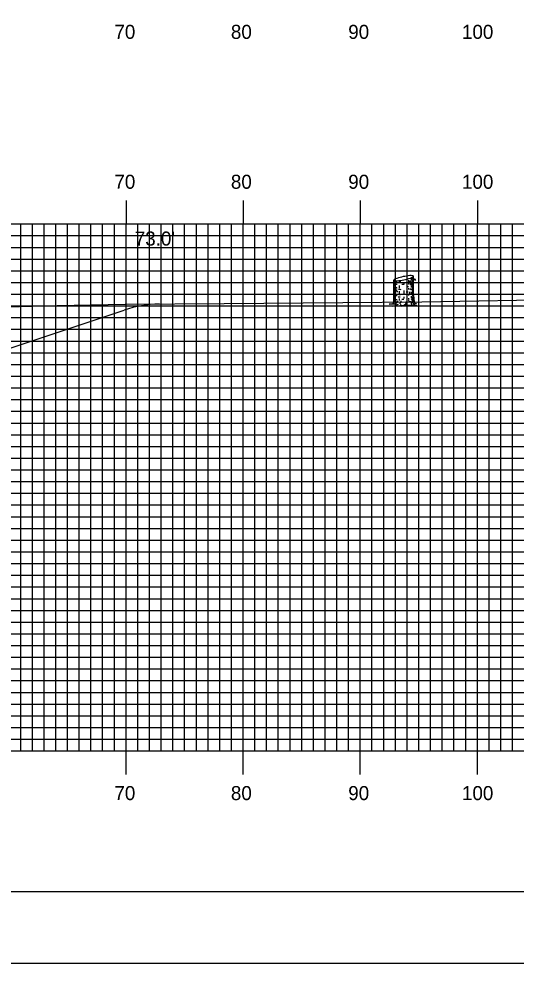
# Model space of a CAD drawing. Extents: x 1795633 to 1795976, y 442591 to 442811.
# Drawn here: x 1795859.7 to 1795902.2, y 442590.5 to 442671.2 of the extents above; entities that cross this region are included whole.
import ezdxf

# ---------------------------------------------------------------- set-up
doc = ezdxf.new("R2010")
doc.units = 0
for name, color, linetype in [('BORDER', 7, 'Continuous'), ('D_Roadway_SlopeLines', 7, 'Continuous'), ('D_Text_Standard', 7, 'Continuous'), ('H_V ANNOTATION', 7, 'Continuous'), ('M_Trees_Conifer_Pay', 7, 'Continuous'), ('MAJOR', 7, 'Continuous'), ('MINOR', 7, 'Continuous'), ('PLOT BOUNDARY', 7, 'Continuous'), ('S_Roadway_Centerline', 7, 'Continuous')]:
    doc.layers.add(name, color=color, linetype=linetype)

msp = doc.modelspace()

# ---------------------------------------------------------------- linework, layer by layer
at = {"layer": 'BORDER'}
msp.add_lwpolyline([(1795649.279, 442596.665), (1795969.279, 442596.665), (1795969.279, 442806.665), (1795649.279, 442806.665)], close=True, dxfattribs=at)
at = {"layer": 'D_Roadway_SlopeLines'}
msp.add_lwpolyline([(1795838.888, 442638.365), (1795844.888, 442638.365), (1795868.728, 442646.312)], dxfattribs=at)
msp.add_arc((1795871.949, 442636.647), 10.187, 91.37379, 108.43495, dxfattribs=at)
at = {"layer": 'M_Trees_Conifer_Pay'}
for p, q in [((1795891.746, 442647.137), (1795891.746, 442648.858)), ((1795891.793, 442648.821), (1795891.793, 442648.35)), ((1795891.852, 442648.81), (1795891.852, 442648.712)), ((1795891.852, 442648.638), (1795891.852, 442648.434)), ((1795891.977, 442648.802), (1795891.977, 442648.57)), ((1795892.197, 442648.822), (1795892.197, 442648.654)), ((1795892.993, 442648.864), (1795892.993, 442648.665)), ((1795893.221, 442649.061), (1795893.221, 442648.837)), ((1795893.221, 442648.749), (1795893.221, 442648.702)), ((1795893.339, 442649.122), (1795893.339, 442648.959)), ((1795893.339, 442648.891), (1795893.339, 442648.763)), ((1795893.41, 442647.547), (1795893.41, 442649.194)), ((1795891.793, 442648.286), (1795891.793, 442647.977)), ((1795891.793, 442647.93), (1795891.793, 442647.438)), ((1795891.852, 442648.376), (1795891.852, 442648.177)), ((1795891.852, 442648.129), (1795891.852, 442647.794)), ((1795891.977, 442648.529), (1795891.977, 442648.455)), ((1795891.977, 442648.051), (1795891.977, 442647.913)), ((1795892.197, 442648.418), (1795892.197, 442648.181)), ((1795892.197, 442647.936), (1795892.197, 442647.784)), ((1795892.603, 442648.591), (1795892.603, 442648.496)), ((1795892.603, 442647.977), (1795892.603, 442647.903)), ((1795892.603, 442647.878), (1795892.603, 442647.73)), ((1795892.993, 442648.607), (1795892.993, 442648.519)), ((1795892.993, 442648.171), (1795892.993, 442648.066)), ((1795893.221, 442648.366), (1795893.221, 442648.234)), ((1795893.221, 442648.124), (1795893.221, 442648.014)), ((1795893.221, 442647.878), (1795893.221, 442647.736)), ((1795893.278, 442648.566), (1795893.227, 442648.506)), ((1795893.339, 442648.576), (1795893.339, 442648.24)), ((1795893.339, 442648.204), (1795893.339, 442648.041)), ((1795893.339, 442647.994), (1795893.339, 442647.777)), ((1795891.793, 442647.384), (1795891.793, 442647.137)), ((1795891.852, 442647.74), (1795891.852, 442647.605)), ((1795891.852, 442647.505), (1795891.852, 442647.127)), ((1795891.977, 442647.641), (1795891.977, 442647.5)), ((1795891.977, 442647.238), (1795891.977, 442647.143)), ((1795892.197, 442647.74), (1795892.197, 442647.567)), ((1795892.197, 442647.29), (1795892.197, 442647.137)), ((1795892.603, 442647.438), (1795892.603, 442647.285)), ((1795892.993, 442647.699), (1795892.993, 442647.553)), ((1795892.993, 442647.32), (1795892.993, 442647.232)), ((1795893.221, 442647.509), (1795893.221, 442647.337)), ((1795893.339, 442647.746), (1795893.339, 442647.672)), ((1795893.339, 442647.631), (1795893.339, 442647.458)), ((1795891.977, 442646.744), (1795892.14, 442646.807)), ((1795892.414, 442646.679), (1795892.288, 442646.744))]:
    msp.add_line(p, q, dxfattribs=at)
for points in [[(1795893.194, 442648.654), (1795893.163, 442648.57), (1795893.159, 442648.502), (1795893.19, 442648.439)], [(1795893.227, 442648.692), (1795893.264, 442648.618), (1795893.311, 442648.675), (1795893.369, 442648.743), (1795893.461, 442648.937), (1795893.526, 442648.984), (1795893.557, 442648.99)], [(1795893.242, 442648.439), (1795893.278, 442648.566), (1795893.342, 442648.681), (1795893.373, 442648.749), (1795893.442, 442648.895)], [(1795893.456, 442648.925), (1795893.532, 442648.933), (1795893.604, 442648.834)], [(1795891.925, 442648.164), (1795891.919, 442648.259), (1795891.963, 442648.236), (1795891.963, 442648.142)], [(1795893.064, 442647.765), (1795893.077, 442647.689), (1795893.124, 442647.699), (1795893.112, 442647.866)], [(1795893.41, 442647.547), (1795893.461, 442647.285), (1795893.478, 442647.011), (1795893.536, 442646.886), (1795893.671, 442646.855), (1795893.441, 442646.818), (1795893.441, 442646.818), (1795893.447, 442646.771), (1795893.694, 442646.676), (1795893.42, 442646.692), (1795893.064, 442646.713), (1795892.743, 442646.702), (1795892.749, 442646.785), (1795892.601, 442646.702), (1795892.414, 442646.679), (1795892.438, 442646.612), (1795892.171, 442646.655), (1795891.95, 442646.628), (1795891.658, 442646.645), (1795891.946, 442646.702), (1795891.977, 442646.744), (1795891.814, 442646.801), (1795891.578, 442646.812), (1795891.337, 442646.812), (1795891.679, 442646.87), (1795891.72, 442646.95), (1795891.746, 442647.137)], [(1795891.794, 442647.089), (1795891.773, 442647.011), (1795891.753, 442646.917)], [(1795891.872, 442647.069), (1795891.878, 442646.954), (1795891.825, 442646.865), (1795891.814, 442646.801)], [(1795892.035, 442647.096), (1795892.035, 442646.964), (1795891.946, 442646.865)], [(1795892.261, 442646.855), (1795892.329, 442646.95), (1795892.356, 442647.089)], [(1795892.749, 442646.785), (1795892.824, 442646.927), (1795892.833, 442647.028)], [(1795893, 442647.154), (1795893.011, 442647.028), (1795893.085, 442646.984)], [(1795893.278, 442646.765), (1795893.264, 442646.902), (1795893.19, 442647.032)], [(1795893.237, 442647.259), (1795893.311, 442647.154), (1795893.316, 442646.981), (1795893.441, 442646.818)], [(1795893.336, 442647.404), (1795893.342, 442647.259), (1795893.389, 442647.19), (1795893.4, 442646.991)]]:
    msp.add_lwpolyline(points, dxfattribs=at)
for centre, radius, start, end in [((1795891.778, 442648.68), 0.0334, 163.94846, 180), ((1795891.778, 442648.68), 0.0334, 180, 196.05154), ((1795891.773, 442648.858), 0.0264, 169.2194, 180.03145), ((1795891.769, 442648.858), 0.0226, 180.03145, 191.7194), ((1795891.789, 442648.683), 0.0441, 196.05154, 210), ((1795891.778, 442648.857), 0.0314, 156.51582, 169.2194), ((1795891.769, 442648.858), 0.0226, 191.7194, 203.40735), ((1795891.772, 442648.86), 0.0264, 203.40735, 214.2194), ((1795891.797, 442648.849), 0.0527, 146.7194, 156.51582), ((1795891.777, 442648.862), 0.0314, 214.2194, 226.92298), ((1795891.805, 442648.692), 0.0624, 210, 228.74941), ((1795891.821, 442648.833), 0.0817, 132.38868, 146.7194), ((1795891.791, 442648.878), 0.0527, 226.92298, 236.7194), ((1795891.807, 442648.902), 0.0817, 236.7194, 251.05013), ((1795891.877, 442648.775), 0.172, 228.74941, 240), ((1795891.935, 442648.708), 0.251, 124.2194, 132.38868), ((1795891.862, 442649.062), 0.251, 251.05013, 259.2194), ((1795892.245, 442648.252), 0.802, 108.05939, 124.2194), ((1795891.965, 442649.603), 0.802, 259.2194, 275.37941), ((1795893.602, 442644.091), 5.179, 101.7194, 108.05939), ((1795891.555, 442653.961), 5.179, 275.37941, 281.7194), ((1795892.578, 442652.87), 4.124, 264.6955, 266.73309), ((1795893.602, 442644.091), 5.179, 95.37941, 101.7194), ((1795891.555, 442653.961), 5.179, 281.7194, 288.05939), ((1795892.578, 442652.87), 4.124, 276.23804, 278.1032), ((1795893.192, 442648.449), 0.802, 79.2194, 95.37941), ((1795892.912, 442649.8), 0.802, 288.05939, 304.2194), ((1795893.079, 442649.353), 0.571, 278.1032, 284.36665), ((1795893.079, 442649.507), 0.571, 284.43166, 292.41325), ((1795893.079, 442649.353), 0.571, 297.0237, 300), ((1795893.295, 442648.99), 0.251, 71.05013, 79.2194), ((1795893.221, 442649.344), 0.251, 304.2194, 312.38868), ((1795893.279, 442649.162), 0.172, 300, 311.25059), ((1795893.279, 442649.008), 0.172, 300, 311.25059), ((1795893.35, 442649.15), 0.0817, 56.7194, 71.05013), ((1795893.335, 442649.219), 0.0817, 312.38868, 326.7194), ((1795893.351, 442649.08), 0.0624, 311.25059, 330), ((1795893.351, 442648.925), 0.0624, 311.25059, 330), ((1795893.366, 442649.174), 0.0527, 46.92298, 56.7194), ((1795893.38, 442649.19), 0.0314, 34.2194, 46.92298), ((1795893.359, 442649.203), 0.0527, 326.7194, 336.51582), ((1795893.367, 442649.07), 0.0441, 330, 343.94846), ((1795893.367, 442648.916), 0.0441, 330, 343.94846), ((1795893.384, 442649.192), 0.0264, 23.40735, 34.2194), ((1795893.388, 442649.194), 0.0226, 11.7194, 23.40735), ((1795893.379, 442649.195), 0.0314, 336.51582, 349.2194), ((1795893.377, 442649.068), 0.0334, 343.94846, 354.21506), ((1795893.377, 442648.913), 0.0334, 343.94846, 354.21506), ((1795893.388, 442649.194), 0.0226, 0.03145, 11.7194), ((1795893.384, 442649.194), 0.0264, 349.2194, 0.03145), ((1795891.778, 442648.233), 0.0334, 163.94846, 180), ((1795891.778, 442648.233), 0.0334, 180, 196.05154), ((1795891.778, 442648.023), 0.0334, 163.94846, 180), ((1795891.778, 442648.023), 0.0334, 180, 196.05154), ((1795891.789, 442648.236), 0.0441, 196.05154, 210), ((1795891.789, 442648.026), 0.0441, 196.05154, 210), ((1795891.805, 442648.246), 0.0624, 210, 228.74941), ((1795891.805, 442648.035), 0.0624, 210, 228.74941), ((1795891.877, 442648.328), 0.172, 228.74941, 240), ((1795891.877, 442648.118), 0.172, 228.74941, 240), ((1795892.076, 442649.12), 0.571, 240, 240.33672), ((1795892.076, 442648.673), 0.571, 240, 240.33672), ((1795892.076, 442648.463), 0.571, 240, 246.85973), ((1795892.078, 442648.909), 0.571, 240, 247.05866), ((1795892.076, 442649.12), 0.571, 246.85973, 257.98457), ((1795892.076, 442648.463), 0.571, 259.27072, 261.8968), ((1795892.577, 442651.981), 4.124, 261.8968, 263.14738), ((1795892.577, 442652.191), 4.124, 264.08098, 266.66759), ((1795892.577, 442652.638), 4.124, 268.07512, 270), ((1795892.577, 442652.638), 4.124, 270, 270.35814), ((1795892.577, 442651.981), 4.124, 270, 270.35814), ((1795892.577, 442651.981), 4.124, 273.14934, 275.45691), ((1795892.578, 442652.426), 4.124, 273.70524, 275.95043), ((1795892.577, 442652.638), 4.124, 275.78493, 277.05584), ((1795892.577, 442652.191), 4.124, 277.61247, 278.1032), ((1795893.078, 442648.673), 0.571, 278.1032, 286.92962), ((1795893.079, 442648.909), 0.571, 284.44928, 297.04285), ((1795893.078, 442648.673), 0.571, 297.18959, 300), ((1795893.078, 442648.463), 0.571, 297.18959, 300), ((1795893.277, 442648.328), 0.172, 300, 311.25059), ((1795893.277, 442648.118), 0.172, 300, 311.25059), ((1795893.35, 442648.246), 0.0624, 311.25059, 330), ((1795893.35, 442648.035), 0.0624, 311.25059, 330), ((1795893.365, 442648.236), 0.0441, 330, 343.94846), ((1795893.365, 442648.026), 0.0441, 330, 343.94846), ((1795893.376, 442648.233), 0.0334, 343.94846, 354.21506), ((1795893.376, 442648.023), 0.0334, 343.94846, 354.21506), ((1795893.377, 442648.469), 0.0334, 343.94846, 354.21506), ((1795891.778, 442647.787), 0.0334, 163.94846, 180), ((1795891.778, 442647.787), 0.0334, 180, 196.05154), ((1795891.778, 442647.589), 0.0334, 163.94846, 180), ((1795891.778, 442647.393), 0.0334, 163.94846, 180), ((1795891.778, 442647.393), 0.0334, 180, 196.05154), ((1795891.778, 442647.173), 0.0334, 163.94846, 180), ((1795891.778, 442647.173), 0.0334, 180, 196.05154), ((1795891.789, 442647.79), 0.0441, 196.05154, 210), ((1795891.789, 442647.396), 0.0441, 196.05154, 210), ((1795891.789, 442647.176), 0.0441, 196.05154, 210), ((1795891.805, 442647.799), 0.0624, 210, 228.74941), ((1795891.805, 442647.405), 0.0624, 210, 228.74941), ((1795891.805, 442647.185), 0.0624, 210, 228.74941), ((1795891.877, 442647.881), 0.172, 228.74941, 240), ((1795891.877, 442647.488), 0.172, 228.74941, 240), ((1795891.877, 442647.268), 0.172, 228.74941, 240), ((1795892.076, 442648.226), 0.571, 240, 246.85973), ((1795892.065, 442648.035), 0.571, 241.23686, 248.02677), ((1795892.076, 442647.833), 0.571, 240, 246.85973), ((1795892.076, 442647.613), 0.571, 240, 244.53138), ((1795892.577, 442651.13), 4.124, 262.44379, 263.51202), ((1795892.577, 442651.546), 4.124, 263.49906, 265.83975), ((1795892.577, 442651.744), 4.124, 264.71603, 266.31934), ((1795892.577, 442651.351), 4.124, 267.81166, 270), ((1795892.577, 442651.351), 4.124, 270, 270.13279), ((1795892.577, 442651.351), 4.124, 275.78493, 276.78961), ((1795892.577, 442651.13), 4.124, 277.36842, 278.1032), ((1795893.078, 442647.613), 0.571, 278.1032, 281.63703), ((1795893.078, 442648.226), 0.571, 285.39827, 297.18959), ((1795893.078, 442647.833), 0.571, 288.50673, 297.27208), ((1795893.078, 442648.029), 0.571, 289.29072, 300), ((1795893.277, 442647.684), 0.172, 300, 311.25059), ((1795893.277, 442647.268), 0.172, 300, 311.25059), ((1795893.35, 442647.601), 0.0624, 311.25059, 330), ((1795893.35, 442647.185), 0.0624, 311.25059, 330), ((1795893.365, 442647.592), 0.0441, 330, 343.94846), ((1795893.365, 442647.176), 0.0441, 330, 343.94846), ((1795893.376, 442647.589), 0.0334, 343.94846, 354.21506), ((1795893.376, 442647.173), 0.0334, 343.94846, 354.21506)]:
    msp.add_arc(centre, radius, start, end, dxfattribs=at)
at = {"layer": 'MAJOR'}
for p, q in [((1795868.879, 442655.669), (1795868.879, 442653.665)), ((1795878.879, 442655.669), (1795878.879, 442653.665)), ((1795888.879, 442655.669), (1795888.879, 442653.665)), ((1795898.879, 442655.669), (1795898.879, 442653.665)), ((1795658.879, 442653.665), (1795938.879, 442653.665)), ((1795658.879, 442653.665), (1795938.879, 442653.665)), ((1795868.879, 442608.665), (1795868.879, 442653.665)), ((1795878.879, 442608.665), (1795878.879, 442653.665)), ((1795888.879, 442608.665), (1795888.879, 442653.665)), ((1795898.879, 442608.665), (1795898.879, 442653.665)), ((1795658.879, 442648.665), (1795938.879, 442648.665)), ((1795658.879, 442643.665), (1795938.879, 442643.665)), ((1795658.879, 442638.665), (1795938.879, 442638.665)), ((1795658.879, 442633.665), (1795938.879, 442633.665)), ((1795658.879, 442628.665), (1795938.879, 442628.665)), ((1795658.879, 442623.665), (1795938.879, 442623.665)), ((1795658.879, 442618.665), (1795938.879, 442618.665)), ((1795658.879, 442613.665), (1795938.879, 442613.665)), ((1795658.879, 442608.665), (1795938.879, 442608.665)), ((1795658.879, 442608.665), (1795938.879, 442608.665)), ((1795868.879, 442606.661), (1795868.879, 442608.665)), ((1795878.879, 442606.661), (1795878.879, 442608.665)), ((1795888.879, 442606.661), (1795888.879, 442608.665)), ((1795898.879, 442606.661), (1795898.879, 442608.665))]:
    msp.add_line(p, q, dxfattribs=at)
at = {"layer": 'MINOR'}
for p, q in [((1795859.879, 442608.665), (1795859.879, 442653.665)), ((1795860.879, 442608.665), (1795860.879, 442653.665)), ((1795861.879, 442608.665), (1795861.879, 442653.665)), ((1795862.879, 442608.665), (1795862.879, 442653.665)), ((1795863.879, 442608.665), (1795863.879, 442653.665)), ((1795864.879, 442608.665), (1795864.879, 442653.665)), ((1795865.879, 442608.665), (1795865.879, 442653.665)), ((1795866.879, 442608.665), (1795866.879, 442653.665)), ((1795867.879, 442608.665), (1795867.879, 442653.665)), ((1795869.879, 442608.665), (1795869.879, 442653.665)), ((1795870.879, 442608.665), (1795870.879, 442653.665)), ((1795871.879, 442608.665), (1795871.879, 442653.665)), ((1795872.879, 442608.665), (1795872.879, 442653.665)), ((1795873.879, 442608.665), (1795873.879, 442653.665)), ((1795874.879, 442608.665), (1795874.879, 442653.665)), ((1795875.879, 442608.665), (1795875.879, 442653.665)), ((1795876.879, 442608.665), (1795876.879, 442653.665)), ((1795877.879, 442608.665), (1795877.879, 442653.665)), ((1795879.879, 442608.665), (1795879.879, 442653.665)), ((1795880.879, 442608.665), (1795880.879, 442653.665)), ((1795881.879, 442608.665), (1795881.879, 442653.665)), ((1795882.879, 442608.665), (1795882.879, 442653.665)), ((1795883.879, 442608.665), (1795883.879, 442653.665)), ((1795884.879, 442608.665), (1795884.879, 442653.665)), ((1795885.879, 442608.665), (1795885.879, 442653.665)), ((1795886.879, 442608.665), (1795886.879, 442653.665)), ((1795887.879, 442608.665), (1795887.879, 442653.665)), ((1795889.879, 442608.665), (1795889.879, 442653.665)), ((1795890.879, 442608.665), (1795890.879, 442653.665)), ((1795891.879, 442608.665), (1795891.879, 442653.665)), ((1795892.879, 442608.665), (1795892.879, 442653.665)), ((1795893.879, 442608.665), (1795893.879, 442653.665)), ((1795894.879, 442608.665), (1795894.879, 442653.665)), ((1795895.879, 442608.665), (1795895.879, 442653.665)), ((1795896.879, 442608.665), (1795896.879, 442653.665)), ((1795897.879, 442608.665), (1795897.879, 442653.665)), ((1795899.879, 442608.665), (1795899.879, 442653.665)), ((1795900.879, 442608.665), (1795900.879, 442653.665)), ((1795901.879, 442608.665), (1795901.879, 442653.665)), ((1795658.879, 442652.665), (1795938.879, 442652.665)), ((1795658.879, 442651.665), (1795938.879, 442651.665)), ((1795658.879, 442650.665), (1795938.879, 442650.665)), ((1795658.879, 442649.665), (1795938.879, 442649.665)), ((1795658.879, 442647.665), (1795938.879, 442647.665)), ((1795658.879, 442646.665), (1795938.879, 442646.665)), ((1795658.879, 442645.665), (1795938.879, 442645.665)), ((1795658.879, 442644.665), (1795938.879, 442644.665)), ((1795658.879, 442642.665), (1795938.879, 442642.665)), ((1795658.879, 442641.665), (1795938.879, 442641.665)), ((1795658.879, 442640.665), (1795938.879, 442640.665)), ((1795658.879, 442639.665), (1795938.879, 442639.665)), ((1795658.879, 442637.665), (1795938.879, 442637.665)), ((1795658.879, 442636.665), (1795938.879, 442636.665)), ((1795658.879, 442635.665), (1795938.879, 442635.665)), ((1795658.879, 442634.665), (1795938.879, 442634.665)), ((1795658.879, 442632.665), (1795938.879, 442632.665)), ((1795658.879, 442631.665), (1795938.879, 442631.665)), ((1795658.879, 442630.665), (1795938.879, 442630.665)), ((1795658.879, 442629.665), (1795938.879, 442629.665)), ((1795658.879, 442627.665), (1795938.879, 442627.665)), ((1795658.879, 442626.665), (1795938.879, 442626.665)), ((1795658.879, 442625.665), (1795938.879, 442625.665)), ((1795658.879, 442624.665), (1795938.879, 442624.665)), ((1795658.879, 442622.665), (1795938.879, 442622.665)), ((1795658.879, 442621.665), (1795938.879, 442621.665)), ((1795658.879, 442620.665), (1795938.879, 442620.665)), ((1795658.879, 442619.665), (1795938.879, 442619.665)), ((1795658.879, 442617.665), (1795938.879, 442617.665)), ((1795658.879, 442616.665), (1795938.879, 442616.665)), ((1795658.879, 442615.665), (1795938.879, 442615.665)), ((1795658.879, 442614.665), (1795938.879, 442614.665)), ((1795658.879, 442612.665), (1795938.879, 442612.665)), ((1795658.879, 442611.665), (1795938.879, 442611.665)), ((1795658.879, 442610.665), (1795938.879, 442610.665)), ((1795658.879, 442609.665), (1795938.879, 442609.665))]:
    msp.add_line(p, q, dxfattribs=at)
at = {"layer": 'PLOT BOUNDARY'}
msp.add_lwpolyline([(1795633.092, 442590.547), (1795973.092, 442590.547), (1795973.092, 442810.547), (1795633.092, 442810.547)], close=True, dxfattribs=at)
at = {"layer": 'S_Roadway_Centerline'}
msp.add_lwpolyline([(1795853.354, 442646.443), (1795862.992, 442646.707), (1795868.789, 442646.817), (1795877.249, 442646.871), (1795894.131, 442647.02), (1795907.074, 442647.226), (1795910.518, 442647.211), (1795915.971, 442647.293), (1795922.426, 442647.336), (1795926.579, 442647.431), (1795938.879, 442647.428)], dxfattribs=at)

# ---------------------------------------------------------------- texts
at = {"layer": 'D_Text_Standard'}
msp.add_text("73.0'", height=1.2, dxfattribs=at).set_placement((1795869.624, 442651.817))
at = {"layer": 'H_V ANNOTATION'}
for s, p in [('70', (1795867.883, 442669.465)), ('80', (1795877.83, 442669.465)), ('90', (1795887.851, 442669.465)), ('100', (1795897.562, 442669.465)), ('70', (1795867.883, 442656.665)), ('80', (1795877.83, 442656.665)), ('90', (1795887.851, 442656.665)), ('100', (1795897.562, 442656.665)), ('70', (1795867.883, 442604.465)), ('80', (1795877.83, 442604.465)), ('90', (1795887.851, 442604.465)), ('100', (1795897.562, 442604.465))]:
    msp.add_text(s, height=1.2, dxfattribs=at).set_placement(p)

doc.saveas('drawing.dxf')
